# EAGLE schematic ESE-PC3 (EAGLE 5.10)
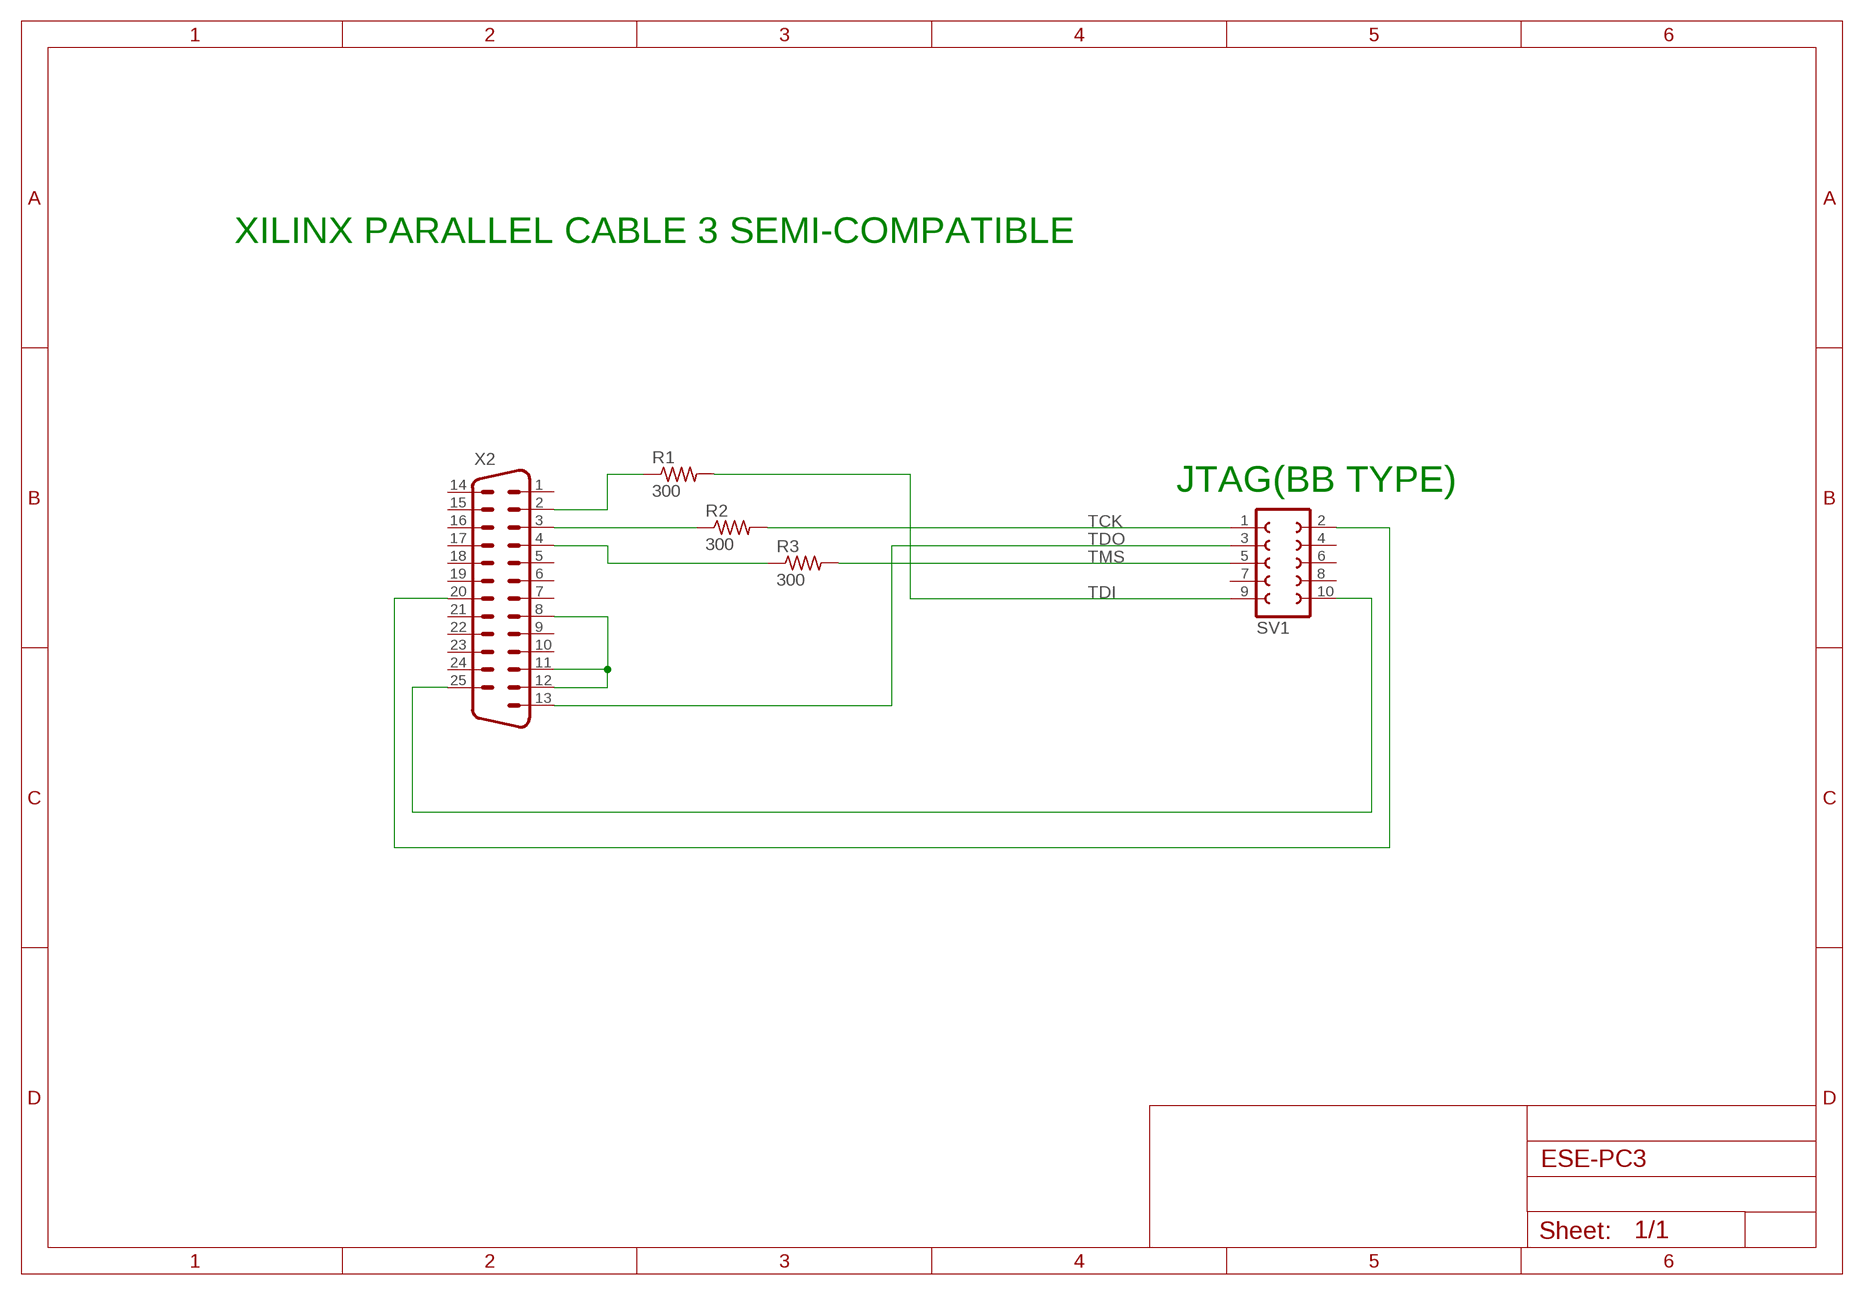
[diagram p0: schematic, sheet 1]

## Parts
R1  300  R-US_0204/5  [0204/5]
R2  300  R-US_0204/5  [0204/5]
R3  300  R-US_0204/5  [0204/5]
SV1  FE05-2  [FE05-2]
X2  M25H  [M25H]

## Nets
N$1: R1.1 X2.2
N$2: R2.1 X2.3
N$3: R3.1 X2.4
N$4: X2.8 X2.11 X2.12
N$9: SV1.10 X2.25
N$10: SV1.2 X2.20
TCK: R2.2 SV1.1
TDI: R1.2 SV1.9
TDO: SV1.3 X2.13
TMS: R3.2 SV1.5
Unconnected: SV1.4 SV1.6 SV1.7 SV1.8 X2.1 X2.5 X2.6 X2.7 X2.9 X2.10 X2.14 X2.15 X2.16 X2.17 X2.18 X2.19 X2.21 X2.22 X2.23 X2.24

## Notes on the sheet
- XILINX PARALLEL CABLE 3 SEMI-COMPATIBLE
- JTAG(BB TYPE)

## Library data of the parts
R1-R3 = adcr:R-US_: RESISTOR, American symbol
SV1 = con-lsta:FE05-2: FEMALE HEADER
X2 = con-subd:M25: SUB-D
